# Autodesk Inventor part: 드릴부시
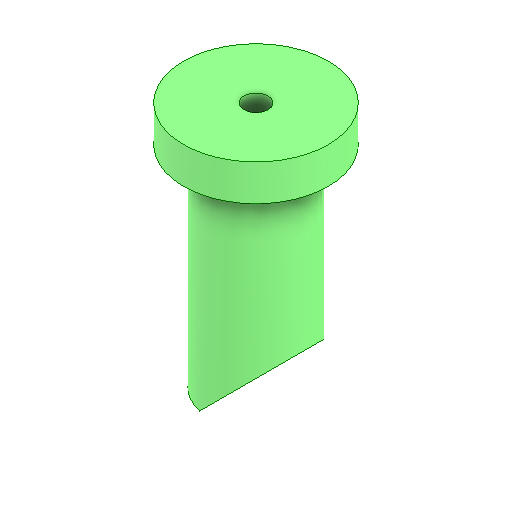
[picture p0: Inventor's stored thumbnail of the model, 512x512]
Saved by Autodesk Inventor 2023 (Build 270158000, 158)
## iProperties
Created: 2025-02
Part Number: 드릴부시
Material: 강철, 합금
Document SubType Name: Modeling
Designer: home
Density: 7.73 g/cm^3
Appearance: 기본값
Author: jhkim
Sending System: Autodesk Inventor 2025
Preprocessor: ST-DEVELOPER v20
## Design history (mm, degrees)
node "드릴부시1"
node "솔리드2"
node "솔리드1"
